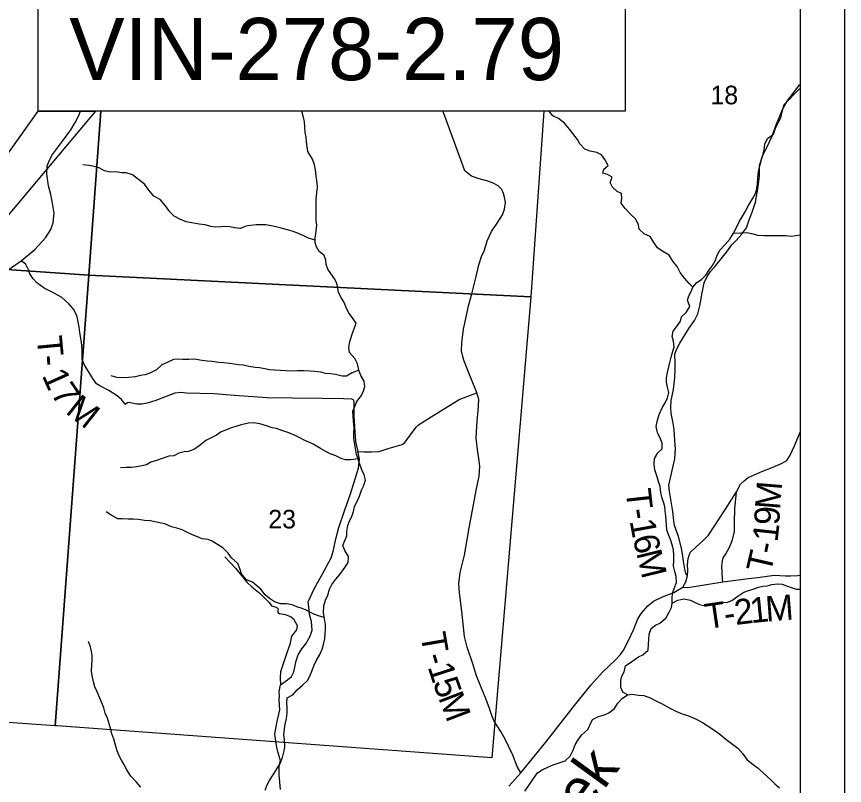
# Model space of a CAD drawing. Extents: x 0 to 34, y 0 to 22.
# Drawn here: x 28.554 to 30.417, y 16.661 to 18.393 of the extents above; entities that cross this region are included whole.
import ezdxf

# ---------------------------------------------------------------- set-up
doc = ezdxf.new("R2010")
doc.units = 0
for name, color, linetype in [('GM_X_County_Road', 7, 'Continuous'), ('GM_X_Minor_River', 7, 'Continuous'), ('GM_X_Minor_River_Text', 7, 'Continuous'), ('GM_X_Section', 7, 'Continuous'), ('GM_X_Section_Text', 7, 'Continuous'), ('GM_X_Township_Road', 7, 'Continuous'), ('GM_X_Township_Road_Text', 7, 'Continuous'), ('SH_Data', 7, 'Continuous'), ('SH_Text', 7, 'Continuous')]:
    doc.layers.add(name, color=color, linetype=linetype)

msp = doc.modelspace()

# ---------------------------------------------------------------- linework, layer by layer
at = {"layer": 'GM_X_County_Road'}
msp.add_lwpolyline([(29.6615, 16.6599), (29.6887, 16.6896), (29.7448, 16.7587), (29.8061, 16.8379), (29.8461, 16.8871), (29.8724, 16.9162), (29.9017, 16.9441), (29.9127, 16.9562), (29.9198, 16.966), (29.9303, 16.9863), (29.9425, 17.0135), (29.9516, 17.0366), (29.9597, 17.049), (29.9745, 17.0655), (29.9873, 17.076), (30.0071, 17.0862), (30.0331, 17.0958), (30.0527, 17.1077), (30.0599, 17.1201), (30.0632, 17.1339), (30.0641, 17.1454), (30.0638, 17.1582), (30.0649, 17.1726), (30.0692, 17.1859), (30.082, 17.1978), (30.0983, 17.2119), (30.1109, 17.2248), (30.1488, 17.2832), (30.1738, 17.3228), (30.1827, 17.3395), (30.191, 17.3474), (30.2001, 17.3545), (30.2311, 17.3686), (30.2538, 17.3774), (30.2664, 17.3827), (30.2769, 17.3867), (30.2871, 17.3932), (30.2936, 17.4032), (30.3043, 17.4261), (30.3167, 17.4567)], dxfattribs=at)
at = {"layer": 'GM_X_Minor_River'}
for points in [[(30.219, 18.002), (30.2212, 18.0152), (30.222, 18.0293), (30.2235, 18.0433), (30.2269, 18.0596), (30.2299, 18.071), (30.234, 18.0828), (30.2359, 18.0926), (30.2374, 18.1055), (30.2438, 18.1184), (30.2567, 18.1279), (30.2616, 18.1412), (30.2684, 18.1549), (30.2733, 18.1643), (30.2767, 18.178), (30.2809, 18.1943), (30.2922, 18.2061), (30.3013, 18.2156), (30.3157, 18.2296), (30.3167, 18.2304)], [(29.3144, 17.2892), (29.3193, 17.299), (29.3254, 17.3127), (29.3299, 17.326), (29.3341, 17.3354), (29.3386, 17.3487), (29.3359, 17.3609), (29.331, 17.3719), (29.3261, 17.3851), (29.3223, 17.3958), (29.3185, 17.4068), (29.3162, 17.4197), (29.3146, 17.4295), (29.3127, 17.4424), (29.3127, 17.4561), (29.3131, 17.4663), (29.3119, 17.4807), (29.3115, 17.494), (29.3108, 17.5039), (29.3146, 17.5145), (29.3195, 17.5255), (29.3297, 17.5395), (29.3342, 17.5498), (29.3376, 17.5593), (29.3357, 17.5718), (29.3281, 17.5843), (29.3239, 17.5964), (29.3209, 17.6108), (29.3148, 17.6226), (29.3031, 17.6359), (29.3011, 17.6476), (29.3034, 17.6613), (29.3102, 17.6818), (29.3143, 17.692), (29.3177, 17.7019), (29.3113, 17.7121), (29.3011, 17.7258), (29.2965, 17.7356), (29.2912, 17.7485), (29.2851, 17.7584), (29.2779, 17.7713), (29.2764, 17.7815), (29.2745, 17.7914), (29.2703, 17.8012), (29.2612, 17.8141), (29.254, 17.824), (29.2506, 17.8346), (29.2494, 17.8441), (29.2456, 17.8547), (29.235, 17.8638), (29.2286, 17.8741), (29.2259, 17.8835), (29.2255, 17.8934), (29.2281, 17.9093), (29.2293, 17.923), (29.2281, 17.9336), (29.2277, 17.9469), (29.2277, 17.9806), (29.2292, 17.9962), (29.2307, 18.0083), (29.2299, 18.0182), (29.2276, 18.0334), (29.2265, 18.0474), (29.2242, 18.0588), (29.2196, 18.0717), (29.2094, 18.0887), (29.2075, 18.099), (29.206, 18.1107), (29.2052, 18.121), (29.2029, 18.1312), (29.2025, 18.1437), (29.2014, 18.1563), (29.1991, 18.1657), (29.1955, 18.1795)], [(30.0757, 17.7834), (30.0674, 17.7917), (30.0571, 17.8035), (30.0469, 17.8164), (30.0401, 17.8297), (30.0306, 17.8422), (30.0219, 17.8551), (30.0082, 17.8634), (29.9957, 17.8718), (29.9878, 17.8839), (29.9794, 17.8972), (29.9662, 17.9032), (29.9548, 17.9138), (29.9536, 17.9233), (29.9472, 17.9362), (29.9354, 17.9476), (29.9233, 17.9605), (29.9142, 17.9726), (29.9161, 17.9829), (29.9153, 17.9939), (29.9051, 17.9984), (29.8948, 18.0083), (29.8892, 18.0189), (29.8937, 18.031), (29.8835, 18.0367), (29.8732, 18.0397), (29.8751, 18.0492), (29.8849, 18.0576), (29.8774, 18.0705), (29.8698, 18.0811), (29.8595, 18.0868), (29.8444, 18.0898), (29.8326, 18.094), (29.8213, 18.1057), (29.816, 18.116), (29.8053, 18.1292), (29.7981, 18.1391), (29.7864, 18.1524), (29.7735, 18.163), (29.7602, 18.169), (29.7519, 18.1795)], [(29.2257, 17.8891), (29.2107, 17.8934), (29.2005, 17.8987), (29.1846, 17.9055), (29.174, 17.9097), (29.1634, 17.9127), (29.149, 17.9161), (29.1369, 17.9188), (29.1263, 17.9214), (29.1149, 17.9233), (29.1028, 17.9237), (29.0926, 17.9233), (29.0805, 17.9222), (29.0706, 17.9203), (29.0566, 17.9153), (29.0452, 17.9168), (29.0335, 17.9195), (29.0233, 17.9202), (29.0131, 17.9191), (29.0013, 17.9183), (28.9911, 17.9202), (28.9778, 17.924), (28.9646, 17.9255), (28.9479, 17.9285), (28.9354, 17.9301), (28.921, 17.9361), (28.9085, 17.9433), (28.899, 17.9528), (28.8892, 17.9668), (28.877, 17.9805), (28.863, 17.9881), (28.8513, 18.0017), (28.8418, 18.015), (28.8278, 18.0256), (28.8149, 18.0366), (28.8001, 18.0404), (28.7903, 18.0411), (28.777, 18.043), (28.7645, 18.0426), (28.7516, 18.0449), (28.741, 18.051), (28.7285, 18.0551), (28.7164, 18.0574), (28.7028, 18.0589)], [(29.9287, 16.865), (29.9181, 16.871), (29.9136, 16.882), (29.9132, 16.8961), (29.9147, 16.9059), (29.9207, 16.9169), (29.9241, 16.931), (29.9385, 16.9405), (29.9532, 16.9511), (29.9631, 16.9556), (29.9748, 16.9659), (29.9759, 16.9796), (29.9767, 16.9898), (29.977, 17.0019), (29.9816, 17.0145), (29.9914, 17.022), (30.0016, 17.027), (30.0149, 17.038), (30.0224, 17.0516), (30.0273, 17.0619), (30.0292, 17.0721), (30.0292, 17.0831), (30.0299, 17.0938), (30.0337, 17.1051), (30.039, 17.118), (30.0378, 17.1317), (30.0352, 17.1431), (30.0321, 17.1552), (30.0325, 17.1677), (30.0329, 17.1795), (30.0321, 17.1909), (30.0298, 17.2011), (30.0253, 17.2151), (30.0199, 17.2277), (30.0173, 17.2371), (30.0165, 17.2478), (30.0154, 17.2576), (30.0146, 17.2675), (30.0134, 17.2796), (30.0123, 17.2895), (30.0093, 17.299), (30.0058, 17.3107), (30.0032, 17.3213), (30.002, 17.3342), (29.9986, 17.346), (29.9952, 17.3562), (29.9899, 17.3722), (29.9883, 17.3851), (29.9895, 17.3976), (29.997, 17.4105), (30.0068, 17.4196), (30.0065, 17.4317), (30.0015, 17.4454), (29.9958, 17.4552), (29.9932, 17.4693), (29.9958, 17.4837), (29.9996, 17.4966), (30.0067, 17.5114), (30.0132, 17.5232), (30.0185, 17.5338), (30.0215, 17.5463), (30.0188, 17.5584), (30.0165, 17.5691), (30.0161, 17.5793), (30.0184, 17.5914), (30.0214, 17.604), (30.024, 17.6134), (30.0267, 17.6256), (30.0304, 17.6389), (30.0338, 17.6483), (30.0319, 17.662), (30.0289, 17.6719), (30.0315, 17.6844), (30.0387, 17.6939), (30.0474, 17.7071), (30.05, 17.7166), (30.0606, 17.7265), (30.0686, 17.7394), (30.0636, 17.7538), (30.0667, 17.7637), (30.0716, 17.7735), (30.0757, 17.7834), (30.0848, 17.7937), (30.095, 17.8009), (30.1048, 17.8104), (30.1113, 17.8206), (30.12, 17.8324), (30.126, 17.8426), (30.1294, 17.8528), (30.1358, 17.8658), (30.1476, 17.8783), (30.1585, 17.8916), (30.1668, 17.9048), (30.1736, 17.9177), (30.1808, 17.9318), (30.1865, 17.942), (30.1933, 17.953), (30.2005, 17.9671), (30.2099, 17.9819), (30.2156, 17.9925), (30.219, 18.002)], [(30.1668, 17.9048), (30.1835, 17.9056), (30.1971, 17.9067), (30.2074, 17.9041), (30.2221, 17.9007), (30.2354, 17.8996), (30.2464, 17.8999), (30.2839, 17.9), (30.2979, 17.8981), (30.3167, 17.9012)], [(29.3239, 17.5965), (29.3092, 17.5903), (29.2963, 17.5831), (29.2861, 17.5831), (29.2713, 17.5869), (29.2599, 17.5884), (29.2486, 17.5888), (29.2384, 17.5918), (29.2247, 17.5933), (29.2137, 17.5945), (29.2001, 17.5952), (29.1857, 17.5952), (29.1732, 17.5945), (29.1596, 17.5952), (29.1478, 17.5956), (29.1338, 17.5963), (29.1232, 17.5971), (29.1126, 17.5994), (29.1001, 17.6016), (29.0903, 17.6024), (29.0763, 17.6043), (29.0638, 17.6073), (29.0532, 17.6084), (29.0339, 17.6111), (29.0191, 17.6126), (29.0092, 17.6137), (28.9941, 17.6156), (28.9827, 17.6168), (28.9664, 17.619), (28.9547, 17.6209), (28.9415, 17.6205), (28.9278, 17.6201), (28.9165, 17.6209), (28.9066, 17.6201), (28.8926, 17.6137), (28.8805, 17.6087), (28.8684, 17.5974), (28.8533, 17.5898), (28.843, 17.586), (28.8317, 17.5844), (28.8215, 17.5814), (28.8056, 17.5799), (28.7931, 17.5791), (28.7791, 17.5802), (28.7669, 17.584)], [(29.322, 17.3964), (29.306, 17.3946), (29.2939, 17.3942), (29.2844, 17.3976), (29.2719, 17.4033), (29.2583, 17.409), (29.2484, 17.4139), (29.2378, 17.42), (29.2211, 17.4295), (29.2116, 17.434), (29.2022, 17.4378), (29.1908, 17.4439), (29.1806, 17.4492), (29.1662, 17.4552), (29.151, 17.4609), (29.1389, 17.4651), (29.1291, 17.4666), (29.1162, 17.4711), (29.101, 17.4753), (29.0878, 17.4776), (29.076, 17.4772), (29.0594, 17.473), (29.0473, 17.4696), (29.0363, 17.4666), (29.0265, 17.462), (29.014, 17.4578), (29.0034, 17.4499), (28.9901, 17.4434), (28.9795, 17.4377), (28.967, 17.4278), (28.9538, 17.4187), (28.9406, 17.4134), (28.9307, 17.4123), (28.919, 17.4092), (28.9076, 17.4035), (28.8966, 17.4024), (28.8838, 17.3982), (28.8686, 17.3933), (28.8558, 17.3895), (28.8459, 17.383), (28.8353, 17.3811), (28.8247, 17.3788), (28.8122, 17.3773), (28.8005, 17.3769), (28.7876, 17.3765)], [(29.1133, 16.6503), (29.1175, 16.6624), (29.1228, 16.6727), (29.1311, 16.6852), (29.147, 16.711), (29.1519, 16.7239), (29.1556, 16.739), (29.1575, 16.7485), (29.1564, 16.7645), (29.1552, 16.7751), (29.1567, 16.7891), (29.1579, 16.799), (29.1612, 16.8119), (29.1624, 16.824), (29.1624, 16.8377), (29.1616, 16.8472), (29.1627, 16.8585), (29.1752, 16.8654), (29.185, 16.8768), (29.1975, 16.887), (29.2081, 16.8976), (29.2138, 16.9071), (29.2179, 16.9189), (29.2232, 16.9325), (29.2277, 16.942), (29.2361, 16.9561), (29.2417, 16.9682), (29.2451, 16.9815), (29.2474, 16.9917), (29.2485, 17.0027), (29.2492, 17.0145), (29.2492, 17.024), (29.2469, 17.0369), (29.2447, 17.0501), (29.2454, 17.0657), (29.2492, 17.0786), (29.2541, 17.0896), (29.2582, 17.1029), (29.2631, 17.1135), (29.2722, 17.126), (29.2809, 17.1363), (29.2907, 17.1499), (29.2998, 17.1632), (29.3009, 17.1769), (29.2926, 17.1905), (29.2876, 17.2015), (29.2926, 17.2129), (29.2971, 17.2235), (29.2971, 17.233), (29.2993, 17.247), (29.3027, 17.2573), (29.3084, 17.2672), (29.3118, 17.2778), (29.3144, 17.2892)], [(29.2465, 17.0397), (29.2325, 17.0429), (29.2197, 17.0482), (29.2056, 17.0562), (29.1962, 17.06), (29.1841, 17.0634), (29.1742, 17.0679), (29.1609, 17.0706), (29.1473, 17.0702), (29.1344, 17.0748), (29.1227, 17.0823), (29.1132, 17.0907), (29.1037, 17.1036), (29.0943, 17.1108), (29.0844, 17.1187), (29.0711, 17.1244), (29.0601, 17.1377), (29.0567, 17.1479), (29.0514, 17.1608), (29.0374, 17.1741), (29.0298, 17.184), (29.018, 17.1961), (29.0059, 17.2037), (28.9942, 17.2112), (28.9847, 17.215), (28.9711, 17.2165), (28.9612, 17.2211), (28.9514, 17.2245), (28.9366, 17.2317), (28.9267, 17.237), (28.9142, 17.2408), (28.9025, 17.2438), (28.8877, 17.2503), (28.876, 17.2529), (28.865, 17.2552), (28.8548, 17.2571), (28.8419, 17.2582), (28.8279, 17.2601), (28.8158, 17.2609), (28.8052, 17.2609), (28.7915, 17.2616), (28.7817, 17.262), (28.7684, 17.2688), (28.7555, 17.2775)], [(30.0292, 17.0721), (30.0421, 17.0782), (30.0549, 17.0813), (30.0705, 17.0782), (30.0807, 17.0729), (30.0902, 17.0684), (30.1034, 17.0661), (30.1163, 17.0695), (30.1277, 17.0722), (30.1424, 17.0729), (30.1534, 17.0741), (30.1632, 17.0779), (30.1765, 17.0874), (30.1901, 17.0965), (30.2011, 17.0999), (30.2113, 17.1033), (30.2234, 17.1075), (30.2333, 17.1098), (30.2431, 17.1105), (30.2533, 17.1136), (30.2666, 17.1155), (30.2768, 17.1144), (30.2863, 17.1109), (30.2988, 17.1064), (30.3082, 17.1034), (30.3167, 17.1034)], [(28.8335, 16.6577), (28.8236, 16.6687), (28.8108, 16.682), (28.8017, 16.6968), (28.7948, 16.7089), (28.7899, 16.7184), (28.785, 16.7279), (28.7804, 16.7389), (28.7758, 16.7552), (28.7728, 16.7654), (28.7682, 16.7776), (28.7656, 16.787), (28.7618, 16.7999), (28.7584, 16.8128), (28.7534, 16.8242), (28.75, 16.8363), (28.7454, 16.8477), (28.7409, 16.858), (28.7348, 16.8724), (28.7302, 16.883), (28.7268, 16.8948), (28.7242, 16.9092), (28.7223, 16.919), (28.7234, 16.9331), (28.7237, 16.9429), (28.7237, 16.9536), (28.7222, 16.9634), (28.7203, 16.9733), (28.7154, 16.9854)], [(29.6976, 16.6483), (29.7078, 16.6634), (29.7173, 16.6771), (29.7256, 16.69), (29.7362, 16.6961), (29.7509, 16.7033), (29.7615, 16.7078), (29.788, 16.717), (29.7994, 16.7272), (29.8058, 16.7394), (29.8111, 16.7526), (29.8186, 16.7652), (29.8255, 16.775), (29.8394, 16.7872), (29.844, 16.7974), (29.8496, 16.8099), (29.8633, 16.8164), (29.8765, 16.8202), (29.8864, 16.8251), (29.8992, 16.8342), (29.9064, 16.8468), (29.9166, 16.8574), (29.9287, 16.865), (29.9389, 16.8665), (29.953, 16.8646), (29.9651, 16.8635), (29.9798, 16.8585), (29.995, 16.8502), (30.0064, 16.8449), (30.0253, 16.8343), (30.0371, 16.8286), (30.0518, 16.8229), (30.0632, 16.8191), (30.0734, 16.8153), (30.0833, 16.8108), (30.0973, 16.8032), (30.1136, 16.7922), (30.1257, 16.7846), (30.1359, 16.7771), (30.1496, 16.7657), (30.1644, 16.7539), (30.1765, 16.7456), (30.1879, 16.7327), (30.1974, 16.7187), (30.211, 16.7088), (30.2227, 16.7005), (30.236, 16.6872), (30.2508, 16.6743), (30.2599, 16.6648), (30.2709, 16.6561)]]:
    msp.add_lwpolyline(points, dxfattribs=at)
at = {"layer": 'GM_X_Section'}
for points in [[(28.7433, 18.1795), (28.7165, 17.8103), (27.7492, 17.8771), (27.8204, 18.905), (28.7909, 18.8364), (28.7636, 18.4595)], [(29.7399, 18.1795), (29.7107, 17.7612), (28.7165, 17.8103), (28.7433, 18.1795)]]:
    msp.add_lwpolyline(points, dxfattribs=at)
for points in [[(27.7492, 17.8771), (28.7165, 17.8103), (28.6406, 16.7957), (27.6556, 16.8655)], [(28.7165, 17.8103), (29.7107, 17.7612), (29.6231, 16.7237), (28.6452, 16.7953), (28.6406, 16.7957)]]:
    msp.add_lwpolyline(points, close=True, dxfattribs=at)
at = {"layer": 'GM_X_Township_Road'}
for points in [[(30.203, 17.9368), (30.2037, 17.9386), (30.2089, 17.9522), (30.2168, 17.9744), (30.2226, 18.0094), (30.2252, 18.0335), (30.2256, 18.0568), (30.2315, 18.0767), (30.2414, 18.0966), (30.2532, 18.1217), (30.2629, 18.1485), (30.2771, 18.1834), (30.2886, 18.2036), (30.3029, 18.2218), (30.3155, 18.2389), (30.3167, 18.2398)], [(28.5641, 17.8427), (28.5946, 17.8684), (28.6189, 17.8944), (28.6306, 17.9129), (28.6364, 17.9285), (28.6384, 17.9499), (28.6354, 17.9676), (28.631, 17.992), (28.6255, 18.0113), (28.6215, 18.0387), (28.6224, 18.0559), (28.6265, 18.0662), (28.6343, 18.0818), (28.657, 18.1119), (28.6759, 18.1378), (28.6858, 18.1542), (28.6936, 18.1695), (28.6976, 18.1795)], [(29.566, 17.7192), (29.5708, 17.7415), (29.5774, 17.7654), (29.5875, 17.8046), (29.5938, 17.8339), (29.6008, 17.8549), (29.606, 17.8647), (29.613, 17.888), (29.6224, 17.9088), (29.6366, 17.9298), (29.6473, 17.9464), (29.6516, 17.9588), (29.6537, 17.974), (29.6519, 17.9861), (29.6494, 17.9944), (29.6459, 18.003), (29.6377, 18.0117), (29.6265, 18.0176), (29.614, 18.0219), (29.5944, 18.0269), (29.5774, 18.0331), (29.5621, 18.0452), (29.5165, 18.1703), (29.5133, 18.1795)], [(30.0632, 17.1339), (30.0599, 17.1382), (30.0575, 17.1482), (30.0544, 17.1666), (30.0525, 17.1826), (30.0494, 17.1983), (30.0434, 17.2217), (30.0346, 17.2465), (30.0324, 17.2575), (30.0305, 17.2782), (30.0262, 17.3049), (30.0229, 17.3233), (30.0215, 17.3371), (30.0315, 17.3801), (30.035, 17.397), (30.0365, 17.4189), (30.0353, 17.4378), (30.0336, 17.4631), (30.0303, 17.4809), (30.0267, 17.4998), (30.0257, 17.5117), (30.0269, 17.5282), (30.0319, 17.5525), (30.0348, 17.579), (30.036, 17.5995), (30.0358, 17.614), (30.0353, 17.6326), (30.0384, 17.6431), (30.0465, 17.6574), (30.0665, 17.6901), (30.0794, 17.7085), (30.0868, 17.723), (30.0913, 17.7416), (30.0963, 17.7707), (30.1009, 17.7927), (30.104, 17.8), (30.1096, 17.8097), (30.1149, 17.8186), (30.1273, 17.8322), (30.1512, 17.8622), (30.1636, 17.8788), (30.1727, 17.8882), (30.1851, 17.9017), (30.1963, 17.9169), (30.203, 17.9368)], [(28.5306, 17.8196), (28.5641, 17.8427)], [(28.7983, 17.5197), (28.7899, 17.53), (28.7802, 17.5386), (28.7615, 17.5507), (28.7413, 17.5608), (28.7337, 17.566), (28.7271, 17.5752), (28.7158, 17.5937), (28.7063, 17.6075), (28.7016, 17.6211), (28.7012, 17.6427), (28.6995, 17.6594), (28.6963, 17.6812), (28.6946, 17.6935), (28.6919, 17.7092), (28.6897, 17.7193), (28.6821, 17.7335), (28.6714, 17.7458), (28.6555, 17.7598), (28.6351, 17.7715), (28.616, 17.7814), (28.5997, 17.7931), (28.5911, 17.8018), (28.5839, 17.8133), (28.5808, 17.8221), (28.5736, 17.8361), (28.5681, 17.8396), (28.5641, 17.8427)], [(29.6218, 16.8233), (29.6181, 16.8347), (29.6107, 16.855), (29.5986, 16.884), (29.5887, 16.9081), (29.5804, 16.9351), (29.5679, 16.9727), (29.5619, 16.9968), (29.5558, 17.0536), (29.5504, 17.0947), (29.5492, 17.1155), (29.5516, 17.1408), (29.5619, 17.1799), (29.5722, 17.2415), (29.5887, 17.3289), (29.5946, 17.3579), (29.5965, 17.3803), (29.5942, 17.3976), (29.5918, 17.4116), (29.5877, 17.4431), (29.5887, 17.4573), (29.5905, 17.4826), (29.5924, 17.5052), (29.5936, 17.53), (29.5891, 17.5452), (29.5874, 17.5511), (29.5706, 17.5921), (29.5601, 17.6192), (29.5576, 17.6274), (29.5549, 17.6398), (29.5556, 17.6577), (29.5593, 17.6884), (29.566, 17.7192)], [(28.7983, 17.5197), (28.8033, 17.5235), (28.8072, 17.5246), (28.813, 17.5229), (28.8243, 17.5204), (28.8354, 17.5209), (28.8482, 17.5227), (28.8677, 17.5289), (28.8909, 17.5379), (28.9107, 17.5457), (28.9235, 17.5468), (28.9361, 17.5455), (28.9983, 17.5435), (29.0433, 17.5401), (29.118, 17.5351), (29.1746, 17.5339), (29.2414, 17.5331)], [(29.2414, 17.5331), (29.2891, 17.5326), (29.3072, 17.5319), (29.3118, 17.5299), (29.313, 17.5253), (29.3129, 17.5127), (29.3127, 17.4921), (29.3161, 17.4359), (29.3214, 17.413), (29.3353, 17.4124), (29.3522, 17.4126), (29.3694, 17.4133), (29.39, 17.4201), (29.4217, 17.4288), (29.4276, 17.4339), (29.4531, 17.4679), (29.458, 17.4733), (29.487, 17.4912), (29.5494, 17.5304), (29.5658, 17.5362), (29.5891, 17.5452)], [(29.1474, 16.652), (29.145, 16.6853), (29.1444, 16.7052), (29.148, 16.717), (29.1444, 16.7272), (29.1419, 16.7368), (29.1385, 16.7514), (29.1349, 16.7776), (29.1398, 16.805), (29.1463, 16.8313), (29.1443, 16.8542), (29.1456, 16.8625), (29.145, 16.8726), (29.1478, 16.8878), (29.1636, 16.8988), (29.1726, 16.9069), (29.1774, 16.9174), (29.1831, 16.9422), (29.1876, 16.9551), (29.1953, 16.9689), (29.205, 16.9799), (29.2143, 16.9977), (29.2192, 17.0111), (29.2176, 17.0302), (29.2131, 17.0464), (29.2111, 17.0638), (29.2098, 17.0748), (29.2237, 17.1039), (29.2415, 17.136), (29.2618, 17.1737), (29.267, 17.1911), (29.2719, 17.2167), (29.2792, 17.2418), (29.2914, 17.2795), (29.3052, 17.318), (29.3234, 17.376), (29.3258, 17.3963), (29.3214, 17.413)], [(30.1429, 17.1196), (30.1421, 17.1265), (30.1414, 17.1408), (30.1409, 17.1551), (30.1419, 17.1673), (30.1438, 17.1739), (30.1488, 17.1814), (30.1584, 17.199), (30.165, 17.2141), (30.1696, 17.2331), (30.1693, 17.2532), (30.1703, 17.2844), (30.1738, 17.3228)], [(29.0221, 17.1761), (29.0347, 17.1631), (29.0461, 17.1502), (29.0594, 17.1348), (29.072, 17.1194), (29.0834, 17.1088), (29.0984, 17.0966), (29.1101, 17.0853), (29.1153, 17.0799), (29.1217, 17.0741), (29.1245, 17.0705), (29.1272, 17.0658), (29.1357, 17.0638), (29.1401, 17.0614), (29.1422, 17.0593), (29.1417, 17.0559), (29.1417, 17.0508), (29.1452, 17.0488), (29.158, 17.046), (29.1719, 17.0411), (29.177, 17.0368), (29.1811, 17.0281), (29.1851, 17.0214), (29.1839, 17.0119), (29.1722, 16.9973), (29.1685, 16.9787), (29.162, 16.9596), (29.1531, 16.9332), (29.1478, 16.917), (29.147, 16.9036), (29.1478, 16.8878)], [(30.0527, 17.1077), (30.0646, 17.107), (30.0787, 17.1091), (30.1429, 17.1196), (30.1945, 17.1262), (30.2271, 17.1304), (30.2532, 17.1339), (30.2625, 17.1351), (30.2712, 17.1341), (30.2842, 17.1335), (30.2954, 17.1335), (30.3119, 17.1339), (30.3167, 17.1346)], [(29.6887, 16.6896), (29.6805, 16.704), (29.6708, 16.7297), (29.6605, 16.7497), (29.6535, 16.7655), (29.6438, 16.7828), (29.6352, 16.7958), (29.6286, 16.806), (29.6239, 16.8167), (29.6218, 16.8233)]]:
    msp.add_lwpolyline(points, dxfattribs=at)
at = {"layer": 'SH_Data'}
for points in [[(23.4167, 21), (30.4167, 21), (30.4167, 14), (23.4167, 14)], [(23.5167, 20.9), (30.3167, 20.9), (30.3167, 14.1), (23.5167, 14.1)], [(28.6022, 18.4595), (29.9232, 18.4595), (29.9232, 18.1795), (28.6022, 18.1795)], [(27.8907, 17.1784), (28.6022, 18.1795), (28.7314, 18.1795), (27.8907, 17.1784)]]:
    msp.add_lwpolyline(points, close=True, dxfattribs=at)

# ---------------------------------------------------------------- texts
at = {"layer": 'GM_X_Minor_River_Text'}
msp.add_text('Creek', height=0.0947, rotation=53.9563, dxfattribs=at).set_placement((29.7139, 16.4281))
at = {"layer": 'GM_X_Section_Text'}
for s, p in [('18', (30.1152, 18.1951)), ('23', (29.1202, 17.2401))]:
    msp.add_text(s, height=0.04186, rotation=0, dxfattribs=at).set_placement(p)
at = {"layer": 'GM_X_Township_Road_Text'}
for s, rotation, p in [('T', 275.4164, (28.5989, 17.6711)), ('-', 274.0784, (28.6029, 17.6291)), ('1', 294.264, (28.6098, 17.5848)), ('7', 304.0326, (28.6293, 17.5437)), ('M', 321.6464, (28.6618, 17.5008)), ('T', 276.3558, (29.9242, 17.3267)), ('M', 85.3273, (30.2716, 17.2809)), ('-', 278.7648, (29.9293, 17.2819)), ('9', 87.6977, (30.2702, 17.2468)), ('1', 280.3571, (29.9331, 17.2572)), ('1', 83.6062, (30.266, 17.2079)), ('6', 282.7193, (29.9399, 17.2202)), ('-', 78.2839, (30.2604, 17.1796)), ('M', 283.7057, (29.9479, 17.1851)), ('T', 76.902, (30.2505, 17.1368)), ('2', 6.7597, (30.1719, 17.0226)), ('1', 5.723, (30.2064, 17.0267)), ('M', 4.4021, (30.2408, 17.0302)), ('T', 8.335, (30.1071, 17.0133)), ('-', 7.8453, (30.149, 17.0195)), ('T', 279.7759, (29.4623, 17.0013)), ('-', 286.8354, (29.4713, 16.952)), ('1', 288.0131, (29.4784, 16.9284)), ('5', 289.689, (29.4898, 16.8934)), ('M', 290.9175, (29.5021, 16.8592))]:
    msp.add_text(s, height=0.0568, rotation=rotation, dxfattribs=at).set_placement(p)
at = {"layer": 'SH_Text'}
msp.add_text('VIN-278-2.79', height=0.14, dxfattribs=at).set_placement((28.6722, 18.2495))

doc.saveas('drawing.dxf')
